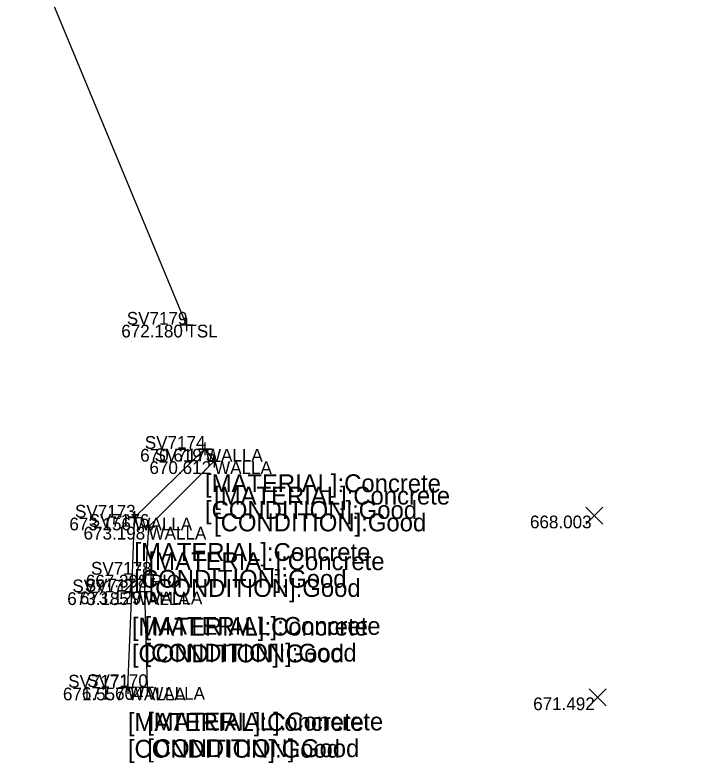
# Model space of a CAD drawing. Extents: x 1660019 to 1662995, y 619975 to 620342.
# Drawn here: x 1661477.1 to 1661530.4, y 620136.2 to 620194.9 of the extents above; entities that cross this region are included whole.
import ezdxf

# ---------------------------------------------------------------- set-up
doc = ezdxf.new("R2010")
doc.units = 0
for name, color, linetype in [('BR_X_Rail_Object', 7, 'Continuous'), ('BR_X_SV_Abut', 7, 'Continuous'), ('BR_X_SV_Abut_Text', 7, 'Continuous'), ('DR_X_Elev_Flow', 7, 'Continuous'), ('RD_P_GR_Lt', 7, 'Continuous'), ('RD_P_GR_Rt', 7, 'Continuous'), ('RD_X_GR_Bar', 7, 'Continuous'), ('RD_X_Wall', 7, 'Continuous'), ('SV_X_Text', 7, 'Continuous'), ('SV_X_Toe_of_Slope', 7, 'Continuous')]:
    doc.layers.add(name, color=color, linetype=linetype)

msp = doc.modelspace()

# ---------------------------------------------------------------- linework, layer by layer
at = {"layer": 'BR_X_SV_Abut'}
msp.add_lwpolyline([(1661487.525, 620142.169), (1661486.009, 620142.126), (1661486.322, 620149.608), (1661486.521, 620155.469), (1661492.058, 620160.869), (1661492.775, 620159.893), (1661487.632, 620154.749), (1661487.32, 620149.668)], close=True, dxfattribs=at)
at = {"layer": 'DR_X_Elev_Flow'}
for p, q in [((1661487.812, 620151.489), (1661487.812, 620150.489)), ((1661487.312, 620150.989), (1661488.312, 620150.989)), ((1661487.812, 620150.989), (1661487.812, 620150.989))]:
    msp.add_line(p, q, dxfattribs=at)
at = {"layer": 'RD_P_GR_Lt'}
for p, q in [((1661490.605, 620171.114), (1661490.605, 620170.114)), ((1661490.105, 620170.614), (1661491.105, 620170.614)), ((1661490.605, 620170.614), (1661490.605, 620170.614)), ((1661491.558, 620160.869), (1661492.558, 620160.869)), ((1661492.058, 620161.369), (1661492.058, 620160.369)), ((1661492.058, 620160.869), (1661492.058, 620160.869)), ((1661492.775, 620160.393), (1661492.775, 620159.393)), ((1661492.275, 620159.893), (1661493.275, 620159.893)), ((1661492.775, 620159.893), (1661492.775, 620159.893)), ((1661486.521, 620155.969), (1661486.521, 620154.969)), ((1661486.021, 620155.469), (1661487.021, 620155.469)), ((1661486.521, 620155.469), (1661486.521, 620155.469)), ((1661487.632, 620155.249), (1661487.632, 620154.249)), ((1661487.132, 620154.749), (1661488.132, 620154.749)), ((1661487.632, 620154.749), (1661487.632, 620154.749)), ((1661486.322, 620150.108), (1661486.322, 620149.108)), ((1661487.32, 620150.168), (1661487.32, 620149.168)), ((1661485.822, 620149.608), (1661486.822, 620149.608)), ((1661486.322, 620149.608), (1661486.322, 620149.608)), ((1661486.82, 620149.668), (1661487.82, 620149.668)), ((1661487.32, 620149.668), (1661487.32, 620149.668)), ((1661487.525, 620142.669), (1661487.525, 620141.669)), ((1661485.509, 620142.126), (1661486.509, 620142.126)), ((1661486.009, 620142.626), (1661486.009, 620141.626)), ((1661486.009, 620142.126), (1661486.009, 620142.126)), ((1661487.025, 620142.169), (1661488.025, 620142.169)), ((1661487.525, 620142.169), (1661487.525, 620142.169))]:
    msp.add_line(p, q, dxfattribs=at)
at = {"layer": 'RD_P_GR_Rt'}
for p, q in [((1661521.958, 620154.963), (1661523.292, 620156.297)), ((1661521.958, 620156.297), (1661523.292, 620154.963)), ((1661522.219, 620140.688), (1661523.553, 620142.024)), ((1661522.219, 620142.024), (1661523.553, 620140.688))]:
    msp.add_line(p, q, dxfattribs=at)
at = {"layer": 'SV_X_Toe_of_Slope'}
msp.add_lwpolyline([(1661490.605, 620170.614), (1661477.149, 620203.096), (1661498.786, 620287.484), (1661510.242, 620298.378), (1661539.687, 620302.32)], dxfattribs=at)

# ---------------------------------------------------------------- texts
at = {"layer": 'BR_X_Rail_Object'}
for s, p in [('TSL', (1661490.605, 620169.614)), ('PIO', (1661487.812, 620149.989))]:
    msp.add_text(s, height=1, dxfattribs=at).set_placement(p)
at = {"layer": 'BR_X_SV_Abut_Text'}
for s, p in [('SV7174', (1661487.338, 620160.869)), ('670.619', (1661486.974, 620159.869)), ('SV7175', (1661488.106, 620159.893)), ('WALLA', (1661492.058, 620159.869)), ('670.612', (1661487.702, 620158.893)), ('WALLA', (1661492.775, 620158.893)), ('SV7173', (1661481.859, 620155.469)), ('SV7176', (1661482.93, 620154.749)), ('673.156', (1661481.417, 620154.469)), ('WALLA', (1661486.521, 620154.469)), ('673.198', (1661482.532, 620153.749)), ('WALLA', (1661487.632, 620153.749)), ('SV7172', (1661481.651, 620149.608)), ('SV7177', (1661482.626, 620149.668)), ('673.129', (1661482.236, 620148.668)), ('673.185', (1661481.252, 620148.608)), ('WALLA', (1661486.322, 620148.608)), ('WALLA', (1661487.32, 620148.668)), ('SV7171', (1661481.329, 620142.126)), ('SV7170', (1661482.813, 620142.169)), ('671.557', (1661480.913, 620141.126)), ('671.604', (1661482.403, 620141.169)), ('WALLA', (1661486.009, 620141.126)), ('WALLA', (1661487.525, 620141.169))]:
    msp.add_text(s, height=1, dxfattribs=at).set_placement(p)
at = {"layer": 'RD_X_GR_Bar'}
for s, p in [('672.180', (1661485.491, 620169.614)), ('668.003', (1661517.561, 620154.63)), ('667.398', (1661482.712, 620149.989)), ('671.492', (1661517.813, 620140.356))]:
    msp.add_text(s, height=1, dxfattribs=at).set_placement(p)
at = {"layer": 'RD_X_Wall'}
for s, p in [('SV7179', (1661485.923, 620170.614)), ('SV7178', (1661483.113, 620150.989))]:
    msp.add_text(s, height=1, dxfattribs=at).set_placement(p)
at = {"layer": 'SV_X_Text'}
for s, p in [('[MATERIAL]:Concrete', (1661492.058, 620157.469)), ('[MATERIAL]:Concrete', (1661492.775, 620156.493)), ('[CONDITION]:Good', (1661492.058, 620155.369)), ('[CONDITION]:Good', (1661492.775, 620154.393)), ('[MATERIAL]:Concrete', (1661486.521, 620152.069)), ('[MATERIAL]:Concrete', (1661487.632, 620151.349)), ('[CONDITION]:Good', (1661486.521, 620149.969)), ('[CONDITION]:Good', (1661487.632, 620149.249)), ('[MATERIAL]:Concrete', (1661486.322, 620146.208)), ('[MATERIAL]:Concrete', (1661487.32, 620146.268)), ('[CONDITION]:Good', (1661486.322, 620144.108)), ('[CONDITION]:Good', (1661487.32, 620144.168)), ('[MATERIAL]:Concrete', (1661486.009, 620138.726)), ('[MATERIAL]:Concrete', (1661487.525, 620138.769)), ('[CONDITION]:Good', (1661486.009, 620136.626)), ('[CONDITION]:Good', (1661487.525, 620136.669))]:
    msp.add_text(s, height=1.4, dxfattribs=at).set_placement(p)

doc.saveas('drawing.dxf')
